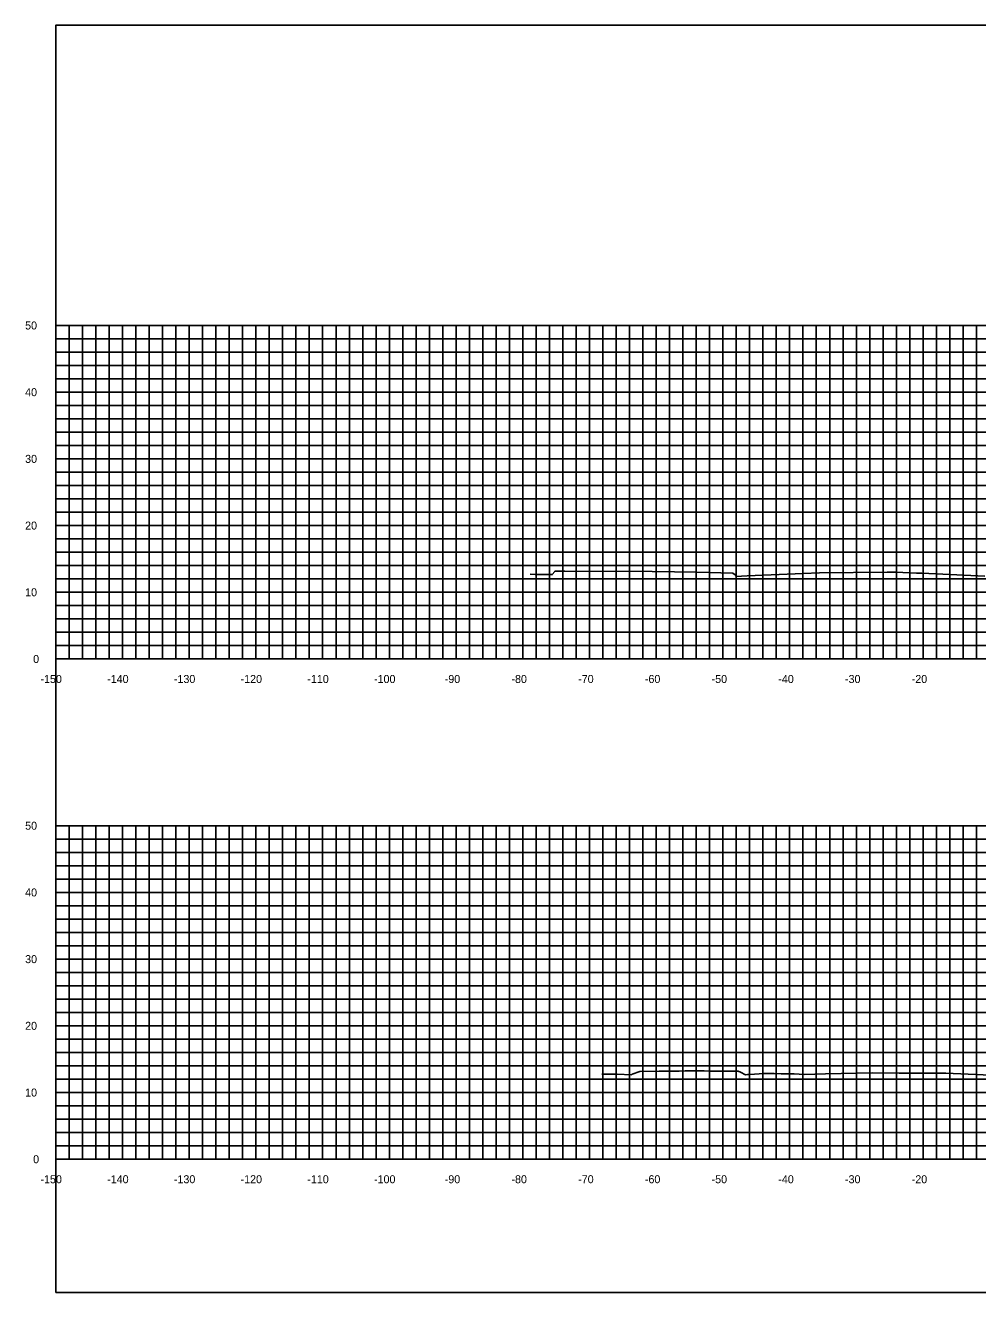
# Model space of a CAD drawing. Extents: x 1797714 to 1804825, y 249015 to 250269.
# Drawn here: x 1803469.6 to 1803612.3, y 249628.2 to 249818.2 of the extents above; entities that cross this region are included whole.
import ezdxf

# ---------------------------------------------------------------- set-up
doc = ezdxf.new("R2010")
doc.units = 0
for name, color, linetype in [('10', 7, 'Continuous'), ('31', 7, 'Continuous'), ('60', 7, 'Continuous'), ('Level 62', 7, 'Continuous'), ('M-ROADS', 7, 'Continuous')]:
    doc.layers.add(name, color=color, linetype=linetype)

msp = doc.modelspace()

# ---------------------------------------------------------------- linework, layer by layer
msp.add_lwpolyline([(1803474.16, 249628.17), (1803774.16, 249628.17), (1803774.16, 249818.17), (1803474.16, 249818.17)], close=True)
at = {"layer": '60'}
for p, q in [((1803474.1, 249773.17), (1803474.16, 249773.17)), ((1803474.16, 249723.17), (1803474.16, 249773.17)), ((1803474.1, 249763.17), (1803474.16, 249763.17)), ((1803474.1, 249753.17), (1803474.16, 249753.17)), ((1803474.1, 249743.17), (1803474.16, 249743.17)), ((1803474.1, 249733.17), (1803474.16, 249733.17)), ((1803474.1, 249723.17), (1803474.16, 249723.17)), ((1803474.16, 249723.17), (1803774.16, 249723.17)), ((1803474.16, 249723.11), (1803474.16, 249723.17)), ((1803484.16, 249723.11), (1803484.16, 249723.17)), ((1803494.16, 249723.11), (1803494.16, 249723.17)), ((1803504.16, 249723.11), (1803504.16, 249723.17)), ((1803514.16, 249723.11), (1803514.16, 249723.17)), ((1803524.16, 249723.11), (1803524.16, 249723.17)), ((1803534.16, 249723.11), (1803534.16, 249723.17)), ((1803544.16, 249723.11), (1803544.16, 249723.17)), ((1803554.16, 249723.11), (1803554.16, 249723.17)), ((1803564.16, 249723.11), (1803564.16, 249723.17)), ((1803574.16, 249723.11), (1803574.16, 249723.17)), ((1803584.16, 249723.11), (1803584.16, 249723.17)), ((1803594.16, 249723.11), (1803594.16, 249723.17)), ((1803604.16, 249723.11), (1803604.16, 249723.17)), ((1803474.1, 249698.17), (1803474.16, 249698.17)), ((1803474.16, 249648.17), (1803474.16, 249698.17)), ((1803474.1, 249688.17), (1803474.16, 249688.17)), ((1803474.1, 249678.17), (1803474.16, 249678.17)), ((1803474.1, 249668.17), (1803474.16, 249668.17)), ((1803474.1, 249658.17), (1803474.16, 249658.17)), ((1803474.1, 249648.17), (1803474.16, 249648.17)), ((1803474.16, 249648.17), (1803774.16, 249648.17)), ((1803474.16, 249648.11), (1803474.16, 249648.17)), ((1803484.16, 249648.11), (1803484.16, 249648.17)), ((1803494.16, 249648.11), (1803494.16, 249648.17)), ((1803504.16, 249648.11), (1803504.16, 249648.17)), ((1803514.16, 249648.11), (1803514.16, 249648.17)), ((1803524.16, 249648.11), (1803524.16, 249648.17)), ((1803534.16, 249648.11), (1803534.16, 249648.17)), ((1803544.16, 249648.11), (1803544.16, 249648.17)), ((1803554.16, 249648.11), (1803554.16, 249648.17)), ((1803564.16, 249648.11), (1803564.16, 249648.17)), ((1803574.16, 249648.11), (1803574.16, 249648.17)), ((1803584.16, 249648.11), (1803584.16, 249648.17)), ((1803594.16, 249648.11), (1803594.16, 249648.17)), ((1803604.16, 249648.11), (1803604.16, 249648.17))]:
    msp.add_line(p, q, dxfattribs=at)
at = {"layer": 'Level 62'}
for p, q in [((1803474.16, 249773.17), (1803774.16, 249773.17)), ((1803474.16, 249723.17), (1803474.16, 249773.17)), ((1803476.16, 249723.17), (1803476.16, 249773.17)), ((1803478.16, 249723.17), (1803478.16, 249773.17)), ((1803480.16, 249723.17), (1803480.16, 249773.17)), ((1803482.16, 249723.17), (1803482.16, 249773.17)), ((1803484.16, 249723.17), (1803484.16, 249773.17)), ((1803486.16, 249723.17), (1803486.16, 249773.17)), ((1803488.16, 249723.17), (1803488.16, 249773.17)), ((1803490.16, 249723.17), (1803490.16, 249773.17)), ((1803492.16, 249723.17), (1803492.16, 249773.17)), ((1803494.16, 249723.17), (1803494.16, 249773.17)), ((1803496.16, 249723.17), (1803496.16, 249773.17)), ((1803498.16, 249723.17), (1803498.16, 249773.17)), ((1803500.16, 249723.17), (1803500.16, 249773.17)), ((1803502.16, 249723.17), (1803502.16, 249773.17)), ((1803504.16, 249723.17), (1803504.16, 249773.17)), ((1803506.16, 249723.17), (1803506.16, 249773.17)), ((1803508.16, 249723.17), (1803508.16, 249773.17)), ((1803510.16, 249723.17), (1803510.16, 249773.17)), ((1803512.16, 249723.17), (1803512.16, 249773.17)), ((1803514.16, 249723.17), (1803514.16, 249773.17)), ((1803516.16, 249723.17), (1803516.16, 249773.17)), ((1803518.16, 249723.17), (1803518.16, 249773.17)), ((1803520.16, 249723.17), (1803520.16, 249773.17)), ((1803522.16, 249723.17), (1803522.16, 249773.17)), ((1803524.16, 249723.17), (1803524.16, 249773.17)), ((1803526.16, 249723.17), (1803526.16, 249773.17)), ((1803528.16, 249723.17), (1803528.16, 249773.17)), ((1803530.16, 249723.17), (1803530.16, 249773.17)), ((1803532.16, 249723.17), (1803532.16, 249773.17)), ((1803534.16, 249723.17), (1803534.16, 249773.17)), ((1803536.16, 249723.17), (1803536.16, 249773.17)), ((1803538.16, 249723.17), (1803538.16, 249773.17)), ((1803540.16, 249723.17), (1803540.16, 249773.17)), ((1803542.16, 249723.17), (1803542.16, 249773.17)), ((1803544.16, 249723.17), (1803544.16, 249773.17)), ((1803546.16, 249723.17), (1803546.16, 249773.17)), ((1803548.16, 249723.17), (1803548.16, 249773.17)), ((1803550.16, 249723.17), (1803550.16, 249773.17)), ((1803552.16, 249723.17), (1803552.16, 249773.17)), ((1803554.16, 249723.17), (1803554.16, 249773.17)), ((1803556.16, 249723.17), (1803556.16, 249773.17)), ((1803558.16, 249723.17), (1803558.16, 249773.17)), ((1803560.16, 249723.17), (1803560.16, 249773.17)), ((1803562.16, 249723.17), (1803562.16, 249773.17)), ((1803564.16, 249723.17), (1803564.16, 249773.17)), ((1803566.16, 249723.17), (1803566.16, 249773.17)), ((1803568.16, 249723.17), (1803568.16, 249773.17)), ((1803570.16, 249723.17), (1803570.16, 249773.17)), ((1803572.16, 249723.17), (1803572.16, 249773.17)), ((1803574.16, 249723.17), (1803574.16, 249773.17)), ((1803576.16, 249723.17), (1803576.16, 249773.17)), ((1803578.16, 249723.17), (1803578.16, 249773.17)), ((1803580.16, 249723.17), (1803580.16, 249773.17)), ((1803582.16, 249723.17), (1803582.16, 249773.17)), ((1803584.16, 249723.17), (1803584.16, 249773.17)), ((1803586.16, 249723.17), (1803586.16, 249773.17)), ((1803588.16, 249723.17), (1803588.16, 249773.17)), ((1803590.16, 249723.17), (1803590.16, 249773.17)), ((1803592.16, 249723.17), (1803592.16, 249773.17)), ((1803594.16, 249723.17), (1803594.16, 249773.17)), ((1803596.16, 249723.17), (1803596.16, 249773.17)), ((1803598.16, 249723.17), (1803598.16, 249773.17)), ((1803600.16, 249723.17), (1803600.16, 249773.17)), ((1803602.16, 249723.17), (1803602.16, 249773.17)), ((1803604.16, 249723.17), (1803604.16, 249773.17)), ((1803606.16, 249723.17), (1803606.16, 249773.17)), ((1803608.16, 249723.17), (1803608.16, 249773.17)), ((1803610.16, 249723.17), (1803610.16, 249773.17)), ((1803612.16, 249723.17), (1803612.16, 249773.17)), ((1803474.16, 249771.17), (1803774.16, 249771.17)), ((1803474.16, 249769.17), (1803774.16, 249769.17)), ((1803474.16, 249767.17), (1803774.16, 249767.17)), ((1803474.16, 249765.17), (1803774.16, 249765.17)), ((1803474.16, 249763.17), (1803774.16, 249763.17)), ((1803474.16, 249761.17), (1803774.16, 249761.17)), ((1803474.16, 249759.17), (1803774.16, 249759.17)), ((1803474.16, 249757.17), (1803774.16, 249757.17)), ((1803474.16, 249755.17), (1803774.16, 249755.17)), ((1803474.16, 249753.17), (1803774.16, 249753.17)), ((1803474.16, 249751.17), (1803774.16, 249751.17)), ((1803474.16, 249749.17), (1803774.16, 249749.17)), ((1803474.16, 249747.17), (1803774.16, 249747.17)), ((1803474.16, 249745.17), (1803774.16, 249745.17)), ((1803474.16, 249743.17), (1803774.16, 249743.17)), ((1803474.16, 249741.17), (1803774.16, 249741.17)), ((1803474.16, 249739.17), (1803774.16, 249739.17)), ((1803474.16, 249737.17), (1803774.16, 249737.17)), ((1803474.16, 249735.17), (1803774.16, 249735.17)), ((1803474.16, 249733.17), (1803774.16, 249733.17)), ((1803474.16, 249731.17), (1803774.16, 249731.17)), ((1803474.16, 249729.17), (1803774.16, 249729.17)), ((1803474.16, 249727.17), (1803774.16, 249727.17)), ((1803474.16, 249725.17), (1803774.16, 249725.17)), ((1803474.16, 249723.17), (1803774.16, 249723.17)), ((1803474.16, 249698.17), (1803774.16, 249698.17)), ((1803474.16, 249648.17), (1803474.16, 249698.17)), ((1803476.16, 249648.17), (1803476.16, 249698.17)), ((1803478.16, 249648.17), (1803478.16, 249698.17)), ((1803480.16, 249648.17), (1803480.16, 249698.17)), ((1803482.16, 249648.17), (1803482.16, 249698.17)), ((1803484.16, 249648.17), (1803484.16, 249698.17)), ((1803486.16, 249648.17), (1803486.16, 249698.17)), ((1803488.16, 249648.17), (1803488.16, 249698.17)), ((1803490.16, 249648.17), (1803490.16, 249698.17)), ((1803492.16, 249648.17), (1803492.16, 249698.17)), ((1803494.16, 249648.17), (1803494.16, 249698.17)), ((1803496.16, 249648.17), (1803496.16, 249698.17)), ((1803498.16, 249648.17), (1803498.16, 249698.17)), ((1803500.16, 249648.17), (1803500.16, 249698.17)), ((1803502.16, 249648.17), (1803502.16, 249698.17)), ((1803504.16, 249648.17), (1803504.16, 249698.17)), ((1803506.16, 249648.17), (1803506.16, 249698.17)), ((1803508.16, 249648.17), (1803508.16, 249698.17)), ((1803510.16, 249648.17), (1803510.16, 249698.17)), ((1803512.16, 249648.17), (1803512.16, 249698.17)), ((1803514.16, 249648.17), (1803514.16, 249698.17)), ((1803516.16, 249648.17), (1803516.16, 249698.17)), ((1803518.16, 249648.17), (1803518.16, 249698.17)), ((1803520.16, 249648.17), (1803520.16, 249698.17)), ((1803522.16, 249648.17), (1803522.16, 249698.17)), ((1803524.16, 249648.17), (1803524.16, 249698.17)), ((1803526.16, 249648.17), (1803526.16, 249698.17)), ((1803528.16, 249648.17), (1803528.16, 249698.17)), ((1803530.16, 249648.17), (1803530.16, 249698.17)), ((1803532.16, 249648.17), (1803532.16, 249698.17)), ((1803534.16, 249648.17), (1803534.16, 249698.17)), ((1803536.16, 249648.17), (1803536.16, 249698.17)), ((1803538.16, 249648.17), (1803538.16, 249698.17)), ((1803540.16, 249648.17), (1803540.16, 249698.17)), ((1803542.16, 249648.17), (1803542.16, 249698.17)), ((1803544.16, 249648.17), (1803544.16, 249698.17)), ((1803546.16, 249648.17), (1803546.16, 249698.17)), ((1803548.16, 249648.17), (1803548.16, 249698.17)), ((1803550.16, 249648.17), (1803550.16, 249698.17)), ((1803552.16, 249648.17), (1803552.16, 249698.17)), ((1803554.16, 249648.17), (1803554.16, 249698.17)), ((1803556.16, 249648.17), (1803556.16, 249698.17)), ((1803558.16, 249648.17), (1803558.16, 249698.17)), ((1803560.16, 249648.17), (1803560.16, 249698.17)), ((1803562.16, 249648.17), (1803562.16, 249698.17)), ((1803564.16, 249648.17), (1803564.16, 249698.17)), ((1803566.16, 249648.17), (1803566.16, 249698.17)), ((1803568.16, 249648.17), (1803568.16, 249698.17)), ((1803570.16, 249648.17), (1803570.16, 249698.17)), ((1803572.16, 249648.17), (1803572.16, 249698.17)), ((1803574.16, 249648.17), (1803574.16, 249698.17)), ((1803576.16, 249648.17), (1803576.16, 249698.17)), ((1803578.16, 249648.17), (1803578.16, 249698.17)), ((1803580.16, 249648.17), (1803580.16, 249698.17)), ((1803582.16, 249648.17), (1803582.16, 249698.17)), ((1803584.16, 249648.17), (1803584.16, 249698.17)), ((1803586.16, 249648.17), (1803586.16, 249698.17)), ((1803588.16, 249648.17), (1803588.16, 249698.17)), ((1803590.16, 249648.17), (1803590.16, 249698.17)), ((1803592.16, 249648.17), (1803592.16, 249698.17)), ((1803594.16, 249648.17), (1803594.16, 249698.17)), ((1803596.16, 249648.17), (1803596.16, 249698.17)), ((1803598.16, 249648.17), (1803598.16, 249698.17)), ((1803600.16, 249648.17), (1803600.16, 249698.17)), ((1803602.16, 249648.17), (1803602.16, 249698.17)), ((1803604.16, 249648.17), (1803604.16, 249698.17)), ((1803606.16, 249648.17), (1803606.16, 249698.17)), ((1803608.16, 249648.17), (1803608.16, 249698.17)), ((1803610.16, 249648.17), (1803610.16, 249698.17)), ((1803612.16, 249648.17), (1803612.16, 249698.17)), ((1803474.16, 249696.17), (1803774.16, 249696.17)), ((1803474.16, 249694.17), (1803774.16, 249694.17)), ((1803474.16, 249692.17), (1803774.16, 249692.17)), ((1803474.16, 249690.17), (1803774.16, 249690.17)), ((1803474.16, 249688.17), (1803774.16, 249688.17)), ((1803474.16, 249686.17), (1803774.16, 249686.17)), ((1803474.16, 249684.17), (1803774.16, 249684.17)), ((1803474.16, 249682.17), (1803774.16, 249682.17)), ((1803474.16, 249680.17), (1803774.16, 249680.17)), ((1803474.16, 249678.17), (1803774.16, 249678.17)), ((1803474.16, 249676.17), (1803774.16, 249676.17)), ((1803474.16, 249674.17), (1803774.16, 249674.17)), ((1803474.16, 249672.17), (1803774.16, 249672.17)), ((1803474.16, 249670.17), (1803774.16, 249670.17)), ((1803474.16, 249668.17), (1803774.16, 249668.17)), ((1803474.16, 249666.17), (1803774.16, 249666.17)), ((1803474.16, 249664.17), (1803774.16, 249664.17)), ((1803474.16, 249662.17), (1803774.16, 249662.17)), ((1803474.16, 249660.17), (1803774.16, 249660.17)), ((1803474.16, 249658.17), (1803774.16, 249658.17)), ((1803474.16, 249656.17), (1803774.16, 249656.17)), ((1803474.16, 249654.17), (1803774.16, 249654.17)), ((1803474.16, 249652.17), (1803774.16, 249652.17)), ((1803474.16, 249650.17), (1803774.16, 249650.17)), ((1803474.16, 249648.17), (1803774.16, 249648.17))]:
    msp.add_line(p, q, dxfattribs=at)
at = {"layer": 'M-ROADS'}
for points in [[(1803545.26, 249735.89), (1803546.02, 249735.86), (1803547.16, 249735.83), (1803547.33, 249735.82), (1803548.57, 249735.82), (1803548.94, 249736.28), (1803548.97, 249736.33), (1803550.2, 249736.34), (1803550.46, 249736.32), (1803563.53, 249736.29), (1803570.25, 249736.21), (1803575.64, 249736.05), (1803575.97, 249735.79), (1803576.2, 249735.54), (1803576.96, 249735.6), (1803577.79, 249735.65), (1803586.21, 249735.99), (1803588.63, 249736.09), (1803598.77, 249736.17), (1803600.11, 249736.18), (1803603.17, 249736.06), (1803603.31, 249736.05), (1803603.97, 249736.05), (1803613.43, 249735.6)], [(1803556.03, 249660.91), (1803556.12, 249660.92), (1803556.27, 249660.92), (1803556.77, 249660.93), (1803557.51, 249660.93), (1803558, 249660.93), (1803558.18, 249660.92), (1803558.3, 249660.92), (1803560.44, 249660.84), (1803560.56, 249660.9), (1803560.84, 249661.02), (1803561.4, 249661.23), (1803561.68, 249661.33), (1803564.62, 249661.37), (1803565.97, 249661.38), (1803567.62, 249661.37), (1803568.5, 249661.41), (1803569.73, 249661.42), (1803570.35, 249661.42), (1803571.36, 249661.42), (1803572.27, 249661.36), (1803573.4, 249661.36), (1803574.19, 249661.37), (1803575.89, 249661.37), (1803576.46, 249661.37), (1803576.78, 249661.22), (1803577.56, 249660.83), (1803577.83, 249660.85), (1803578.19, 249660.87), (1803579.59, 249660.97), (1803580.23, 249661.01), (1803581.86, 249661), (1803582.9, 249660.99), (1803584.17, 249660.97), (1803584.82, 249660.96), (1803586.35, 249660.89), (1803589.53, 249660.96), (1803596.53, 249661.1), (1803600.56, 249661.08), (1803607.58, 249661.07), (1803616.53, 249660.68)]]:
    msp.add_lwpolyline(points, dxfattribs=at)

# ---------------------------------------------------------------- texts
at = {"layer": '10'}
for s, p in [('-150', (1803471.86, 249719.57)), ('-140', (1803481.86, 249719.57)), ('-130', (1803491.86, 249719.57)), ('-120', (1803501.86, 249719.57)), ('-110', (1803511.86, 249719.57)), ('-100', (1803521.86, 249719.57)), ('-90', (1803532.46, 249719.57)), ('-80', (1803542.46, 249719.57)), ('-70', (1803552.46, 249719.57)), ('-60', (1803562.46, 249719.57)), ('-50', (1803572.46, 249719.57)), ('-40', (1803582.46, 249719.57)), ('-30', (1803592.46, 249719.57)), ('-20', (1803602.46, 249719.57)), ('-150', (1803471.86, 249644.57)), ('-140', (1803481.86, 249644.57)), ('-130', (1803491.86, 249644.57)), ('-120', (1803501.86, 249644.57)), ('-110', (1803511.86, 249644.57)), ('-100', (1803521.86, 249644.57)), ('-90', (1803532.46, 249644.57)), ('-80', (1803542.46, 249644.57)), ('-70', (1803552.46, 249644.57)), ('-60', (1803562.46, 249644.57)), ('-50', (1803572.46, 249644.57)), ('-40', (1803582.46, 249644.57)), ('-30', (1803592.46, 249644.57)), ('-20', (1803602.46, 249644.57))]:
    msp.add_text(s, height=1.2, dxfattribs=at).set_placement(p)
at = {"layer": '31'}
for s, p in [('50', (1803469.56, 249772.57)), ('40', (1803469.56, 249762.57)), ('30', (1803469.56, 249752.57)), ('20', (1803469.56, 249742.57)), ('10', (1803469.56, 249732.57)), ('0', (1803470.76, 249722.57)), ('50', (1803469.56, 249697.57)), ('40', (1803469.56, 249687.57)), ('30', (1803469.56, 249677.57)), ('20', (1803469.56, 249667.57)), ('10', (1803469.56, 249657.57)), ('0', (1803470.76, 249647.57))]:
    msp.add_text(s, height=1.2, dxfattribs=at).set_placement(p)
at = {"layer": '60'}
for p in [(1803474.16, 249723.17), (1803474.16, 249648.17)]:
    msp.add_text('-', height=0.0001, dxfattribs=at).set_placement(p)

doc.saveas('drawing.dxf')
